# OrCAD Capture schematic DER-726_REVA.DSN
size C; title: DER 726; rev: A
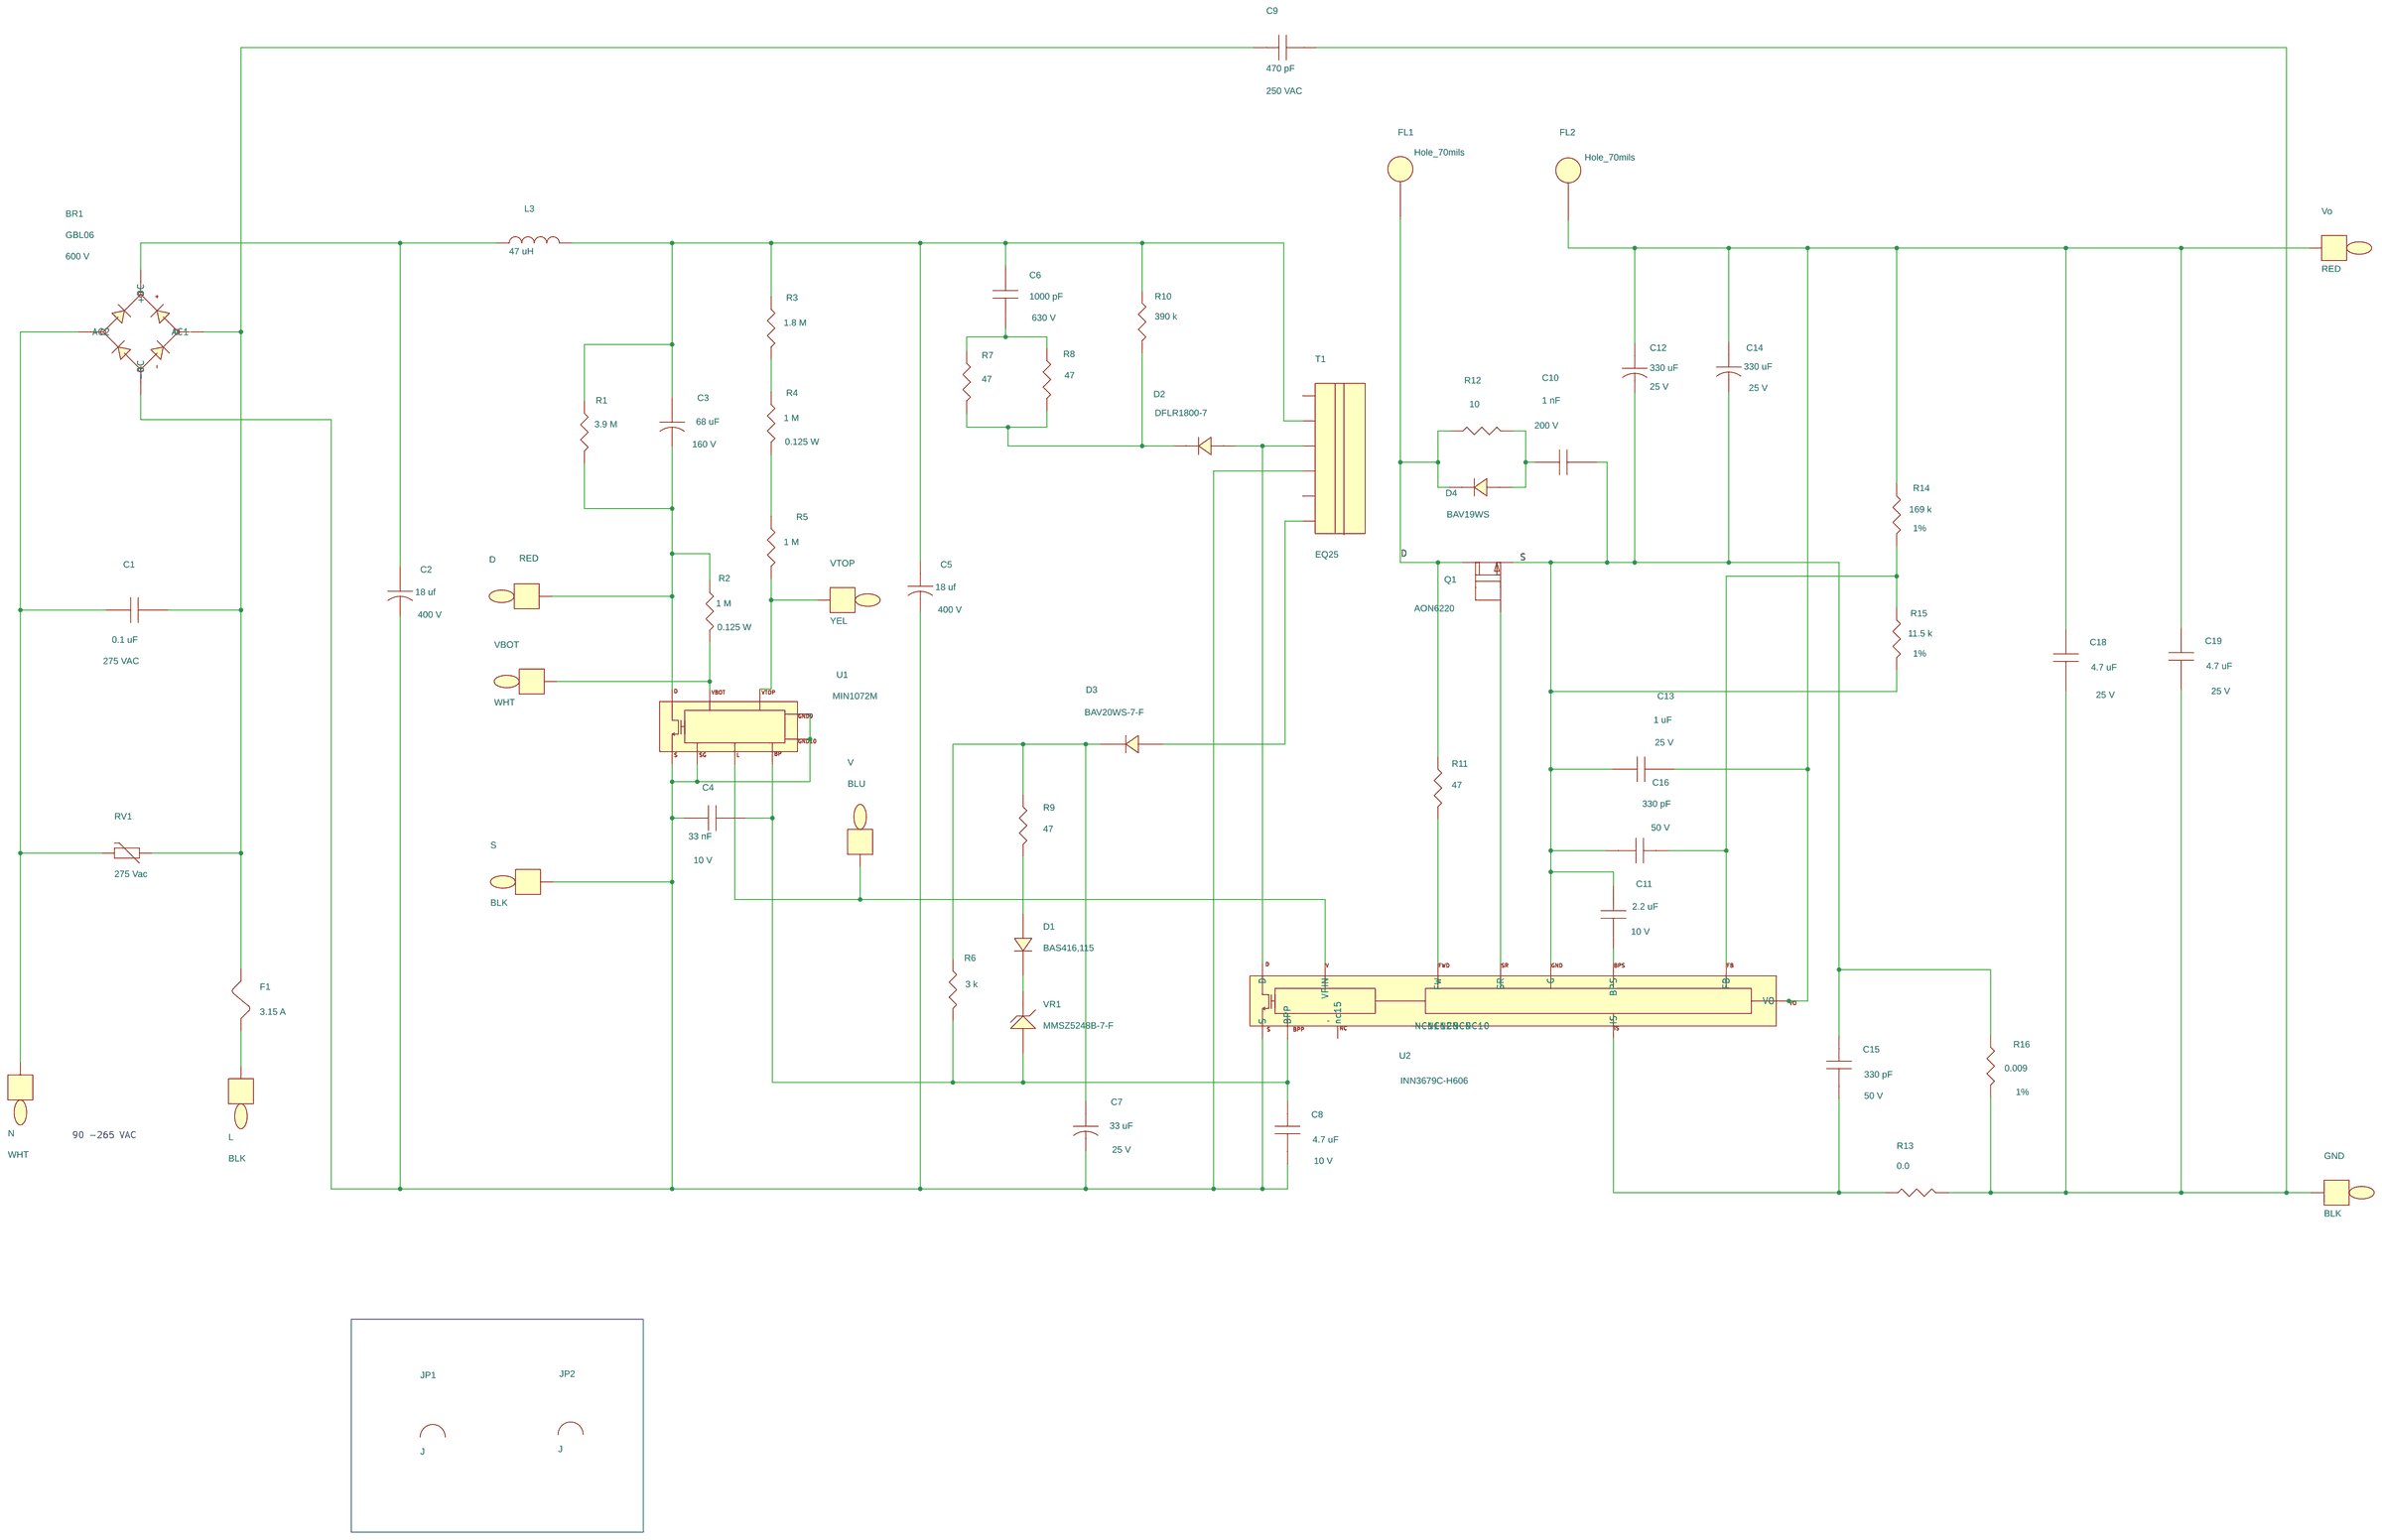
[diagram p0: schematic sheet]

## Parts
BR1  GBL06  [pidaxbridgegbl06]
C1  0.1 uF  [pinpxcaprad13x7LS10mmD040]
C2  18 uf  [pipolcapcyld400ls200040]
C3  68 uF  [pipolcapcyld400ls200040]
C4  33 nF  [pismc0805]
C5  18 uf  [pipolcapcyld400ls200040]
C6  1000 pF  [pismc1206]
C7  33 uF  [pipolcapclyd200ls80030]
C8  4.7 uF  [pismc0805]
C9  470 pF  [pinpcaprad374x275ls394d040]
C10  1 nF  [pismc0805]
C11  2.2 uF  [pismc0805]
C12  330 uF  [pipolcapcyld315ls138d030]
C13  1 uF  [pismc0805]
C14  330 uF  [pipolcapcyld315ls138d030]
C15  330 pF  [pismc0603]
C16  330 pF  [pismc0603]
C18  4.7 uF  [pismc0805]
C19  4.7 uF  [pismc0805]
D  RED  [pitpkeystone125x125]
D1  BAS416,115  [pismdsod323]
D2  DFLR1800-7  [pismddflr120012]
D3  BAV20WS-7-F  [pismdsod323]
D4  BAV19WS  [pismsod323]
F1  3.15 A  [pi_rst_microfuse]
FL1  Hole_70mils  [pi_hole_70mil]
FL2  Hole_70mils  [pi_hole_70mil]
GND  BLK  [pitpkeystone125x125]
JP1  J  [pi_jumper1000-18awg-sld]
JP2  J  [pi_jumper400]
L  BLK  [pitpkeystone125x125]
L3  47 uH  [pichoketokinvd345h453ls197d030]
N  WHT  [pitpkeystone125x125]
Q1  AON6220  [pismpqfn5x6b]
R1  3.9 M  [pismr1206]
R2  1 M  [pi18wvresd80ls100d030]
R3  1.8 M  [pismr1206]
R4  1 M  [pi18wvresd80ls100d030]
R5  1 M  [pismr1206]
R6  3 k  [pismr0603]
R7  47  [pismr1206]
R8  47  [pismr1206]
R9  47  [pismr0603]
R10  390 k  [pismr1206]
R11  47  [pismr0603]
R12  10  [pismr1206]
R13  0.0  [pismr0603]
R14  169 k  [pismr0603]
R15  11.5 k  [pismr0603]
R16  0.009  [pismr0805]
RV1  275 Vac  [pidisc350x160ls210x140040]
S  BLK  [pitpkeystone125x125]
T1  EQ25  [pi_bobbin_eq-25_6p]
U1  MIN1072M  [PI_SM_MinSOP16A_1]
U2  INN3679C-H606  [pi_ic_insop_24d]
V  BLU  [pitpkeystone125x125]
VBOT  WHT  [pitpkeystone125x125]
Vo  RED  [pitpkeystone125x125]
VR1  MMSZ5248B-7-F  [pi_sm_sod-123_12]
VTOP  YEL  [pitpkeystone125x125]

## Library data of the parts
BR1 = DISCRETE_BRIDGE_+~~-: Disp_Voltage: 600 V; Part Number: 15-01112-00
C1 = CAP_NP: ALT_SYMBOLS: pinpxcaprad13x7LS10mmD040H; Disp_Voltage: 275 VAC; FPLIST: pinpxcaprad13x7LS10mmD040,pinpxcaprad13x7LS10mmD040H; Part Number: 20-01458-00; Voltage: 275 VAC
C2 C5 = CAP_POL: ALT_SYMBOLS: pipolcapclyd395x630ls200030h; Disp_Voltage: 400 V; FPLIST: pipolcapcyld400ls200040,pipolcapclyd395x630ls200030h; Part Number: 20-09063-00; Voltage: 400 V
C3 = CAP_POL: ALT_SYMBOLS: pipolcapcyld10x20x5mmlsd30h; Disp_Voltage: 160 V; FPLIST: pipolcapcyld400ls200040,pipolcapcyld10x20x5mmlsd30h; Part Number: 20-01499-00; Voltage: 160 V
C4 = CAP_NP: Disp_Voltage: 10 V; Part Number: 20-01401-00; Voltage: 10 V
C6 = CAP_NP: Disp_Voltage: 630 V; Part Number: 20-08616-00; Voltage: 630 V
C7 = CAP_POL: ALT_SYMBOLS: pipolcapclyd200ls80030h; Disp_Voltage: 25 V; FPLIST: pipolcapclyd200ls80030,pipolcapclyd200ls80030h; Part Number: 20-00807-00; Voltage: 25 V
C8 = CAP_NP: Disp_Voltage: 10 V; Part Number: 20-00612-00; Voltage: 10 V
C9 = CAP_NP: Disp_Voltage: 250 VAC; Part Number: 20-09075-00; Voltage: 250 VAC
C10 = CAP_NP: ALT_SYMBOLS: pismc0805_1; Disp_Voltage: 200 V; FPLIST: pismc0805,pismc0805_1; PCB Editor PCBFP: pismc0603; Part Number: 20-00737-00; ROOM: 2; Voltage: 200 V
C11 = CAP_NP: Disp_Voltage: 10 V; Part Number: 20-08747-00; Voltage: 10 V
C12 C14 = CAP_POL: ALT_SYMBOLS: pipolcapcyld315ls138d030h; Disp_Voltage: 25 V; FPLIST: pipolcapcyld315ls138d030,pipolcapcyld315ls138d030h; Part Number: 20-09107-00; ROOM: 2; Voltage: 25 V
C13 = CAP_NP: Disp_Voltage: 25 V; Part Number: 20-00923-00; ROOM: 2; Voltage: 25 V
C15 C16 = CAP_NP: Disp_Voltage: 50 V; Part Number: 20-08676-00; Voltage: 50 V
C18 C19 = CAP_NP: Disp_Voltage: 25 V; Part Number: 20-09022-00; Voltage: 25 V
D Vo = TESTPOINT: Part Number: 35-00043-00
D1 = DIODE: Part Number: 15-01164-00
D2 = DIODE: COMPGROUP: 2; Part Number: 15-00919-00; ROOM: 1
D3 = DIODE: Part Number: 15-00712-00
D4 = DIODE: Part Number: 15-00658-00; ROOM: 2
F1 = FUSE: ALT_SYMBOLS: pirstmicrofusehoz; COMPGROUP: 1; FPLIST: pi_rst_microfuse,pirstmicrofusehoz; Part Number: 40-00020-00; ROOM: 1
FL1 FL2 = FlyingLead: Part Number: 35-00282-00; ROOM: 2
GND L S = TESTPOINT: Part Number: 35-00042-00
JP1 = JUMPER_1: Part Number: 65-00168-00
JP2 = JUMPER_1: Part Number: 65-00400-02
L3 = INDUCTOR: ALT_SYMBOLS: pichoketokinvd345h453ls197d030H; FPLIST: pichoketokinvd345h453ls197d030,pichoketokinvd345h453ls197d030H; Part Number: 30-04098-00
N VBOT = TESTPOINT: Part Number: 35-00044-00
Q1 = FET_N_SGD_123_4_5678: Part Number: 50-00276-00; ROOM: 2
R1 = R: Part Number: 05-01435-00
R2 R4 = R: ALT_SYMBOLS: pi18wresd080ls300d030; Disp_Power: 0.125 W; FPLIST: pi18wvresd80ls100d030,pi18wresd080ls300d030; Part Number: 05-02409-00
R3 = R: Part Number: 05-01427-00
R5 = R: Part Number: 05-01424-00
R6 = R: Part Number: 05-01699-00
R7 R8 = R: Part Number: 05-01320-00
R9 = R: ALT_SYMBOLS: pismr0603_1; Part Number: 05-01656-00; ROOM: 1
R10 = R: Part Number: 05-01414-00
R11 = R: ALT_SYMBOLS: pismr0603_1; Part Number: 05-01656-00; ROOM: 2
R12 = R: Part Number: 05-01304-00
R13 = R: Part Number: 05-03158-00
R14 = R: Disp_Tol: 1%; Part Number: 05-01196-00
R15 = R: Disp_Tol: 1%; Part Number: 05-03188-00
R16 = R: Disp_Tol: 1%; Part Number: 05-06508-00
RV1 = VARISTOR: ALT_SYMBOLS: pi_disc_354x220_ls220x10_040_h; FPLIST: pidisc350x160ls210x140040,pi_disc_354x220_ls220x10_040_h; Part Number: 85-00015-00; ROOM: 1
T1 = BEQ25_6P: Part Number: 25-01136-00
U1 = MinE-CAP: Part Number: 10-01091-00
U2 = Inno3EP_P15: Part Number: 10-01050-03
V = TESTPOINT: Part Number: 35-00185-00
VR1 = DIODE_ZENER: Part Number: 15-01105-00
VTOP = TESTPOINT: Part Number: 35-00046-00

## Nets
D: D4.1 FL1.1 Q1.5(D) Q1.6(D) Q1.7(D) Q1.8(D) R11.1 R12.1
NC8: U2.8(NC8)
NC9: U2.9(NC9)
NC10: U2.10(NC10)
NC11: U2.11(NC11)
NC12: U2.12(NC12)
S: C10.2 C11.1 C12.2 C13.1 C14.2 C15.1 C16.2 Q1.1(S) Q1.2(S) Q1.3(S) R15.2 R16.1 U2.2(G)
N11525368: BR1.2(AC1) C1.2 C9.1 F1.2 RV1.1
N11525664: BR1.3(AC2) C1.1 N.1 RV1.2
N11525782: C3.1 C5.1 C6.1 L3.2 R1.1 R3.1 R10.1 T1.2
N11525810: C9.2 C18.2 C19.2 GND.1 R13.2 R16.2
N11525884: C6.2 R7.1 R8.1
N11526002: D2.1 R7.2 R8.2 R10.2
N11526006: C12.1 C13.2 C14.1 C18.1 C19.1 FL2.1 R14.1 U2.6(VO) Vo.1
N11526148: D2.2 T1.3 U2.24(D)
N11526230: BR1.4(-DC) C2.2 C4.1 C5.2 C7.2 C8.2 S.1 T1.4 U1.3 U1.9 U1.10 U1.11 U2.16(S)
N11526330: C16.1 R14.2 R15.1 U2.3(FB)
N11526430: D3.2 T1.6
N11526456: C10.1 D4.2 R12.2
N11526718: Q1.4(G) U2.5(SR)
N11526838: C7.1 D3.1 R6.1 R9.1
N11527062: D1.2 R9.2
N11527294: C15.2 R13.1 U2.1(IS)
N11527492: C4.2 C8.1 R6.2 U1.4 U2.14(BPP) VR1.2
N11532941: R3.2 R4.1
N11533086: C3.2 D.1 R1.2 R2.1 U1.16
N11543266: R4.2 R5.1
N11556072: R5.2 U1.8 VTOP.1
N11567872: U1.5 U2.13(VPIN) V.1
N11568750: BR1.1(+DC) C2.1 L3.1
N12363198: R2.2 U1.1 VBOT.1
N12366027: C11.2 U2.4(BPS)
N12367034: F1.1 L.1
N12372611: D1.1 VR1.1
N12385908: R11.2 U2.7(FW)

Not connected (* = marked no-connect by the designer): JP1 1 2; JP2 1 2; T1 1 5; U2 15(nc15)

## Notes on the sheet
- 90 -265 VAC
